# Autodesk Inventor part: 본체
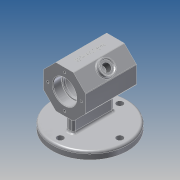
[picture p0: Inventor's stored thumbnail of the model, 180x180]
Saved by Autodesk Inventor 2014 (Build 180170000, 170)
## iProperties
Created: 2021-02
Part Number: 본체
Material: 알루미늄 6061
Document SubType Name: Modeling
Designer: kb542-18
Density: 2.71 g/cm^3
Appearance: 알루미늄 - 평지
Mass: 558.806 g
Surface Area: 509.67 cm^2
Volume: 206.202 cm^3
Author: kb542-18
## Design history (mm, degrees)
sketch "스케치1"
  geometry: L1 (12.012, 29)-(29, 12.012); L2 (29, 12.012)-(29, -12.012); L3 (29, -12.012)-(12.012, -29); L4 (12.012, -29)-(-12.012, -29); L5 (-12.012, -29)-(-29, -12.012); L6 (-29, -12.012)-(-29, 12.012); L7 (-29, 12.012)-(-12.012, 29); L8 (-12.012, 29)-(12.012, 29); 3 further points
  constraints: 16 end point, 1 coincident, 1 midpoint, 1 vertical alignment, 17 other
  dimensions: "d0" = 58 distance between parallel lines of L4 L8
extrude "돌출1" new body sketch "스케치1" stored distance "d1" = 70; taper "d2" = 0 deg
sketch "스케치2"
  geometry: L1 (-35, 29)-(-35, 12.012) reference; L2 (-35, 12.012)-(-35, -12.012) reference; L3 (-35, -12.012)-(-35, -29) reference; L4 (35, 12.012)-(35, 29) reference; L5 (35, -12.012)-(35, 12.012) reference; L6 (35, -29)-(35, -12.012) reference; L7 (-35, 16)-(-23, 16); L8 (-23, 16)-(-23, 14); L9 (-23, 14)-(-20, 14); L10 (-20, 14)-(-20, 22); L11 (-20, 22)-(20, 22); L12 (20, 22)-(20, 14); L13 (20, 14)-(23, 14); L14 (23, 14)-(23, 16); L15 (23, 16)-(35, 16); L16 (-35, 0)-(35, 0); 2 further points
  constraints: 20 end point, 6 parallel, 3 midpoint, 3 perpendicular, 2 point on line, 1 vertical alignment
  dimensions: "d3" = 32 diameter of L7 L16; "d4" = 28 diameter of L9 L16; "d5" = 44 diameter of L11 L16; "d6" = 28 diameter of L13 L16; "d7" = 32 diameter of L15 L16; "d8" = 12 distance from line of L2 L8.end; "d9" = 40 distance between parallel lines of L12 L10; "d10" = 12 distance between parallel lines of L4 L14
revolve "회전1" sketch "스케치2" stored, may be unused: angle "d11" = 90 deg
sketch "스케치3"
  geometry: L1 (12.012, 29)-(-12.012, 29) reference; L2 (0, 23)-(0, -23); L3 (-23, 0)-(23, 0); C1 r 16 at (0, 0) reference; A1 r 23 centre (0, 0) between (0, 23) and (0, -23); 5 further points
  constraints: 5 coincident, 5 point on circle, 4 end point, 2 midpoint, 2 perpendicular, 1 centre point
  dimensions: "d12" = 46 diameter of A1
hole "구멍1" sketch "스케치3" at (0, 23), (-23, 0), (0, -23), (23, 0) diameter "d13" = 3.242; stored, may be unused: countersink angle "d17" = 90 deg, drill point angle "d19" = 118 deg; dims "d14" = 8, "d15" = 4, "d16" = 2, "d18" = 10
node "작업 평면1"
sketch "스케치4"
  geometry: L1 (-52, 0)-(52, 0); L2 (0, -52)-(0, 52); C1 r 4.5 at (-41, 0); C2 r 4.5 at (0, -41); C3 r 4.5 at (41, 0); C4 r 4.5 at (0, 41); A1 r 52 centre (0, 0) between (-52, 0) and (52, 0); A2 r 41 centre (0, 0) between (-41, 0) and (0, -41); 2 further points
  constraints: 8 point on circle, 6 centre point, 4 end point, 4 point on line, 3 coincident, 3 equal radius, 2 midpoint, 1 horizontal, 1 perpendicular
  dimensions: "d21" = 104 diameter of A1; "d22" = 82 diameter of A2; "d23" = 9 diameter of C3
extrude "돌출2" join sketch "스케치4" distance "d24" = 10; taper "d25" = 0 deg
sketch "스케치5"
  geometry: L1 (-5, -28)-(5, -28); L2 (5, -28)-(5, 28); L3 (5, 28)-(-5, 28); L4 (-5, 28)-(-5, -28); C1 r 52 at (0, 0) reference; 2 further points
  constraints: 8 end point, 2 midpoint, 2 parallel, 1 horizontal, 1 horizontal alignment, 1 perpendicular, 1 vertical alignment
  dimensions: "d26" = 10 distance between parallel lines of L2 L4; "d27" = 56 distance between parallel lines of L3 L1
extrude "돌출3" join sketch "스케치5" stored distance "d28" = 10; taper "d29" = 0 deg
sketch "스케치6"
  geometry: L1 (0, 0)-(-24.024, 0) reference; L2 (-41.012, 0)-(-41.012, 70) reference; C1 r 10 at (-12.012, 35); 1 further point
  constraints: 1 centre point
  dimensions: "d30" = 20 diameter of C1; "d31" = 29 distance from line of C1.centre L2; "d32" = 35 distance from line of C1.centre L1
extrude "돌출4" join sketch "스케치6" distance "d33" = 5; taper "d34" = 0 deg
hole "구멍2" diameter "d37" = 10.917; stored, may be unused: countersink angle "d41" = 90 deg, drill point angle "d43" = 118 deg; dims "d35" = 10, "d36" = 10, "d38" = 15, "d39" = 16, "d40" = 2, "d42" = 8
sketch "스케치7"
  geometry: L1 (24.024, -70)-(0, -70) reference; L2 (-16.988, 0)-(-16.988, -70) reference; 2 further points
  constraints: 1 other
  dimensions: "d44" = 35 distance from line of point (12.012, -35) L1; "d45" = 29 distance from line of point (12.012, -35) L2
feature "엠보싱1" sketch "스케치7" dims "d0" = 58, "d3" = 32, "d4" = 28, "d5" = 44, "d6" = 28, "d7" = 32, "d8" = 12, "d9" = 40, "d10" = 12, "d46" = 0.5, "d47" = 0
chamfer "모따기1" distance "d48" = 1; stored, may be unused: second distance "d49" = 2, angle "d50" = 45 deg
fillet "모깎기1" dims "d51" = 0.3, "d52" = 1, "d53" = 3
fillet "모깎기2" dims "d54" = 3
node "솔리드1"
mirror "대칭1"
other parameters: "d20" = -62
